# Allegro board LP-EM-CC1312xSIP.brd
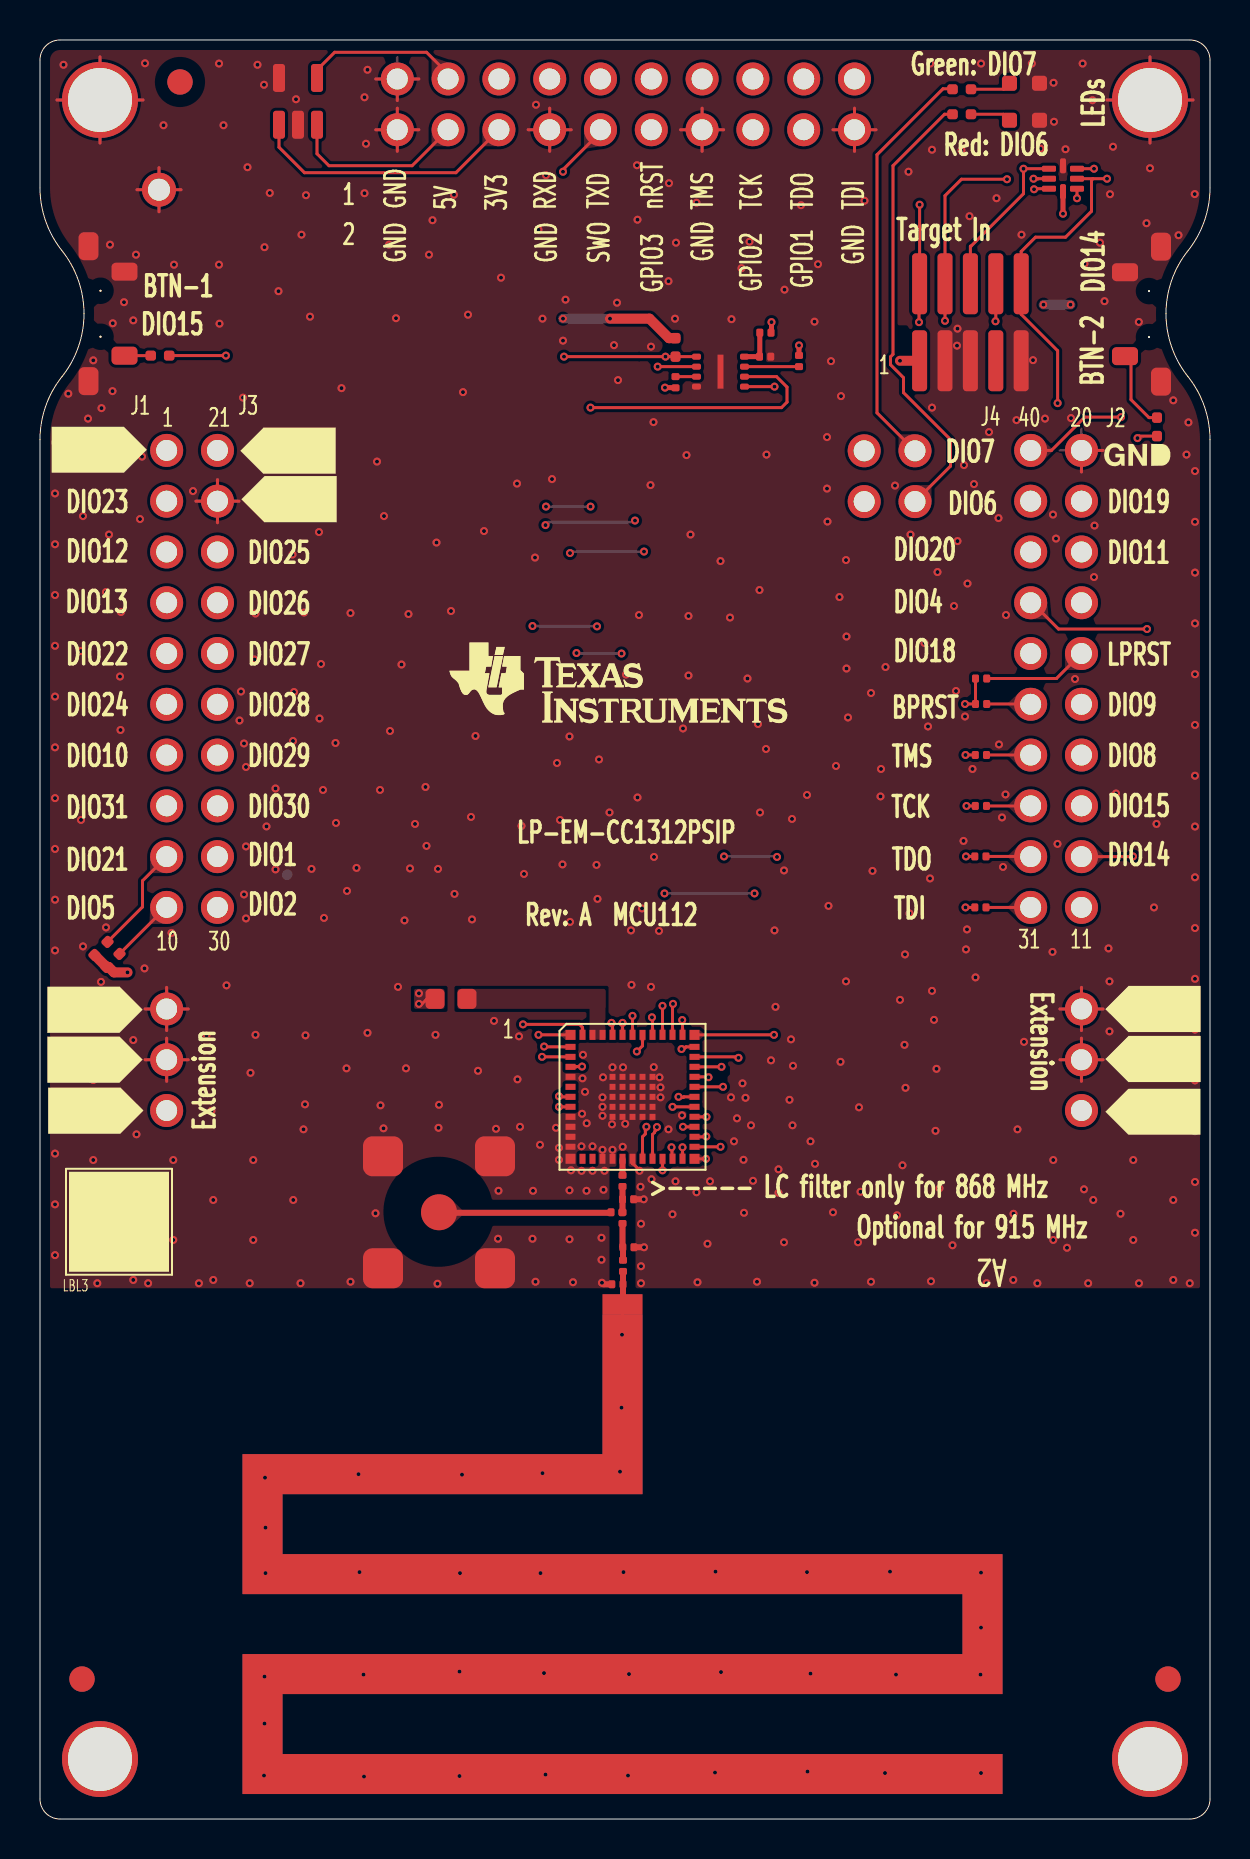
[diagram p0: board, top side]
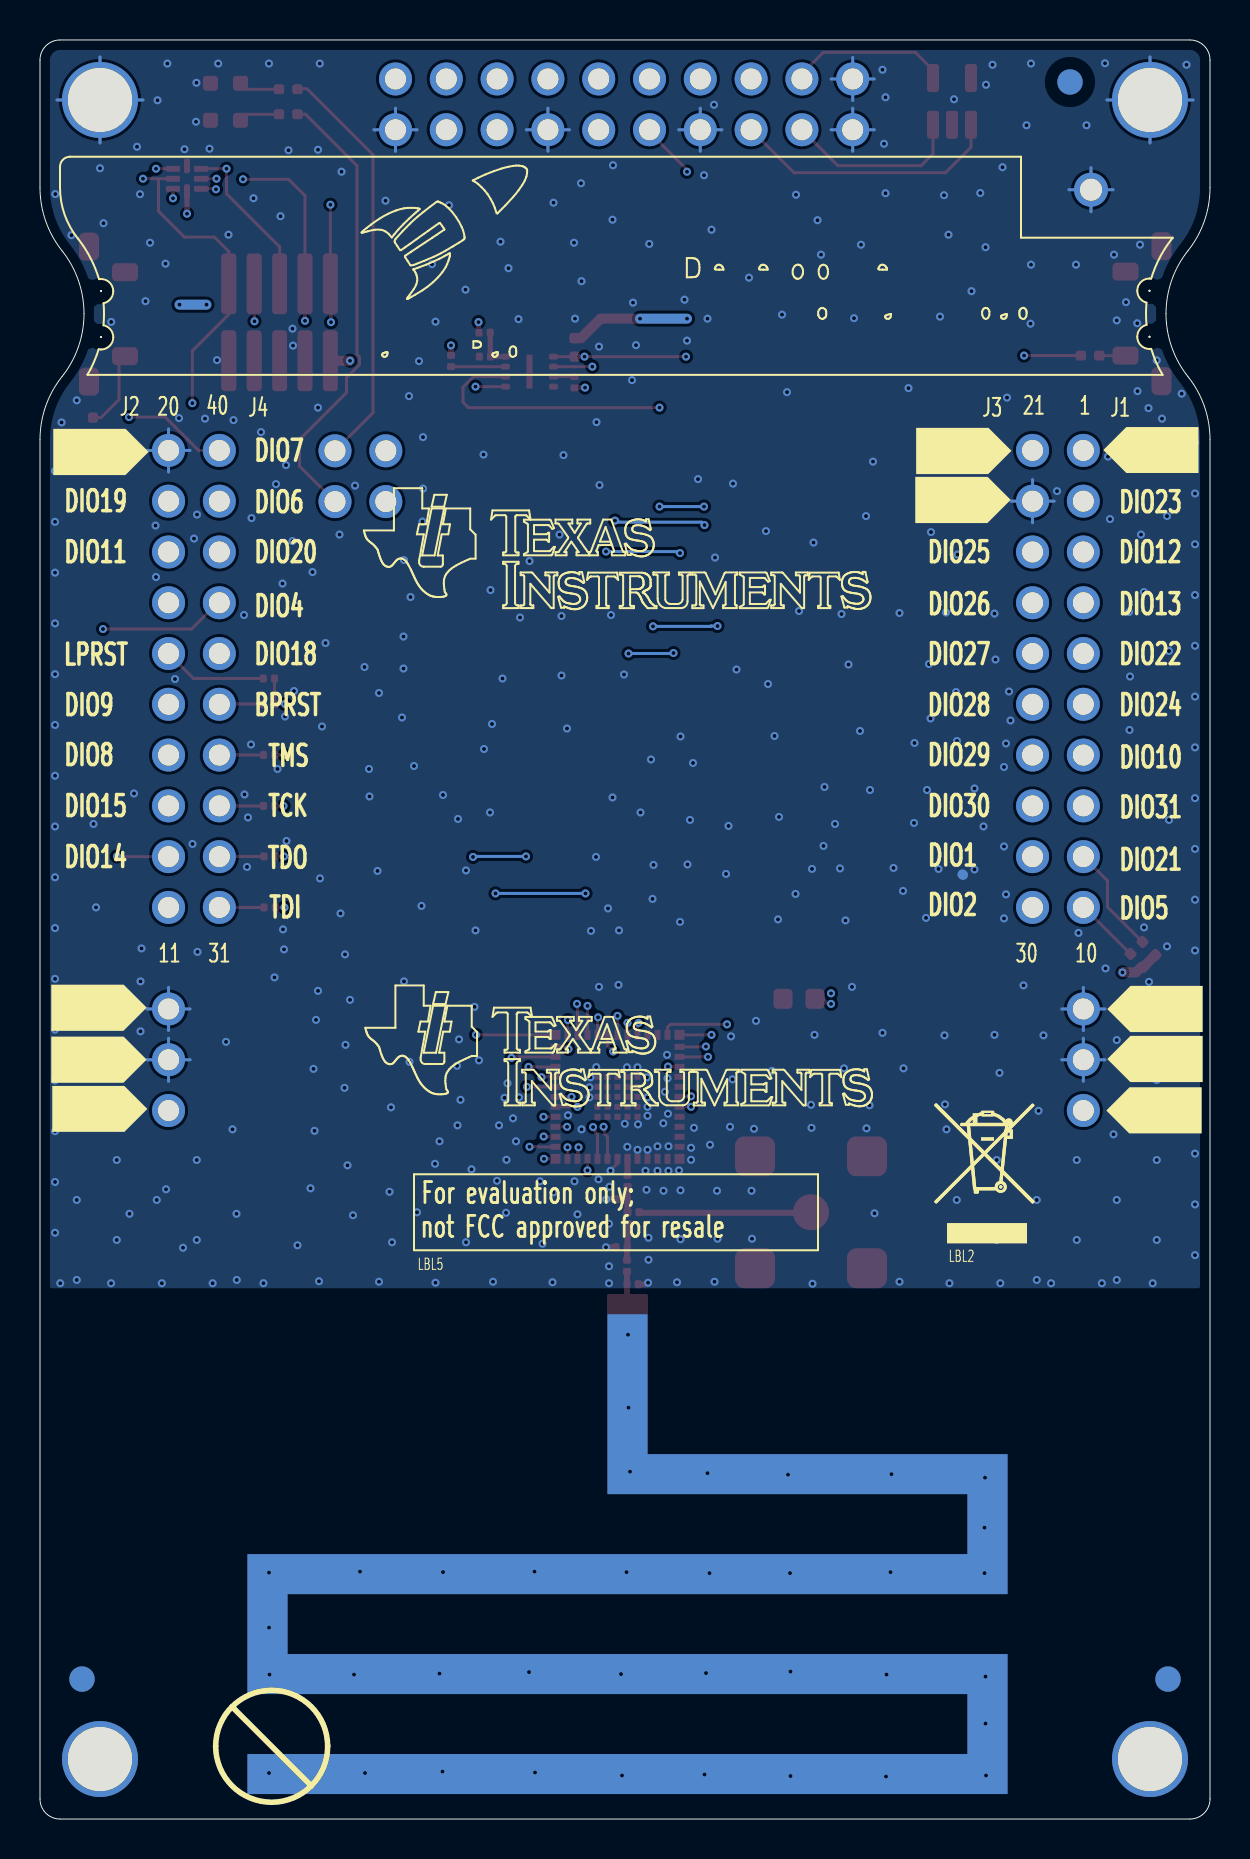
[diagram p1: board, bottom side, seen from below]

Outline 58.5 x 88.99 mm; copper layers: TOP, L2, L3, BOTTOM. Coordinates in mm from the lower left corner of the outline.
Outline path: 0,87.99 0,81.6 arc(0.28,79.93) 1.1,78.45 arc(1.92,76.97) 2.2,75.3 arc(1.92,73.63) 1.1,72.15 arc(0.28,70.67) 0,69 0,1 arc(0.29,0.29) 1,0 57.5,0 arc(58.21,0.29) 58.5,1 58.5,69 arc(58.22,70.67) 57.4,72.15 arc(56.58,73.63) 56.3,75.3 arc(56.58,76.97) 57.4,78.45 arc(58.22,79.93) 58.5,81.6 58.5,87.99 arc(58.21,88.7) 57.5,88.99 1,88.99 arc(0.29,88.7) 0,87.99

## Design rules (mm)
constraint set DEFAULT: min track width 0.15
nets with their own width: min track width 0.15; nets GND VDDS WMCU_VDD

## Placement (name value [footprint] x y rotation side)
A2  868MHz/2440MHz  [ANTENNA_DN024N]  29.12 25.75 180 top
C1  1.8pF  [CAPC0603X35B2N]  29.12 31 0 top
C55  0.1uF  [CAPC0603X35B2N]  35.97 73.15 0 top
C56  100pF  [CAPC0603X35B2N]  28.55 30.35 0 top
C57  100pF  [CAPC0603X35B2N]  29.12 30.35 270 top
CR2  TPD6E004RSE  [QFNFC50P150X150X60-8A2N]  51.85 81.55 90 top
CR4  LPL296-J2L2-25  [LEDC1707X65N]  49.97 86.82 180 top
CR5  LS L296-P2Q2-1  [LEDC1708X67N]  49.97 84.98 180 top
FIDU1  FIDU_1.27mm  [FID127X142]  7 86.89 0 top
FIDU2  FIDU_1.27mm  [FID127X142]  2.1 7 0 top
FIDU3  FIDU_1.27mm  [FID127X142]  56.4 7 0 top
FIDU4  FIDU_1.27mm  [FID127X142]  7 86.89 180 bottom
FIDU5  FIDU_1.27mm  [FID127X142]  2.1 7 180 bottom
FIDU6  FIDU_1.27mm  [FID127X142]  56.4 7 180 bottom
FL2  BLM18HE152SN1  [FIL_BLM18HE152SN1DN]  21.35 41.03 180 top
J1  SSQ-110-23-L-D  [SAMTEC_SSQ11023LD_A2B]  6.33 68.46 0 bottom
J2  SSQ-110-23-L-D  [SAMTEC_SSQ11023LD_A2B]  49.53 68.46 0 bottom
J4  SFH11-PBPC-D10-RA-BK  [SULLINS_SFH11PBPCD10RABK_A2B]  40.72 84.5 90 top
J5  SMA-10V21-TGG  [HUSTSAN_SMA10V21TGGAN]  19.95 30.35 0 top
L1  5.6nH  [INDC0603X33A2N]  29.12 32.2 270 top
LBL1  TI_LOGO  [TI_LOGO_1]  21.47 58.85 0 top
LBL2  TRASH_7mm  [TRASH_7MM]  13.15 28.8 180 bottom
LBL3  ESD_LABEL_5x5mm  [ESD_LABEL_5X5]  1.45 27.38 0 top
LBL5  -  [LABEL_FOR_EVALUATION_ONLY]  39.65 28.6 180 bottom
M1  SNT-100-BK-G  [SAMTEC_SNT100BKG]  44.97 67.18 180 top
M2  SNT-100-BK-G  [SAMTEC_SNT100BKG]  44.97 69.7 180 top
M3  DCB-10  [MECH_DCB10_A2B]  2.86 85.55 180 bottom
M4  DCB-10  [MECH_DCB10_A2B]  55.57 85.79 180 bottom
M5  DCB-10  [MECH_DCB10_A2B]  3 3 180 bottom
M6  DCB-10  [MECH_DCB10_A2B]  55.5 3 180 bottom
MH1  HOLE_3.2mm_PAD_3.8mm_PTH  [MTG320_380]  3 3 0 top
MH2  HOLE_3.2mm_PAD_3.8mm_PTH  [MTG320_380]  55.5 3 0 top
MH3  HOLE_3.2mm_PAD_3.8mm_PTH  [MTG320_380]  3 85.99 0 top
MH4  HOLE_3.2mm_PAD_3.8mm_PTH  [MTG320_380]  55.5 85.99 0 top
MH5  HOLE_1.1mm_PTH  [MTG110_170]  5.95 81.5 0 top
NOREF  -  []  0 85.11 0 top
NOREF#2  -  []  0.02 -28.78 0 top
NOREF#3  -  []  54.51 0 90 top
NOREF#4  -  []  -4.35 67.3 0 top
NOREF#5  -  []  -1.95 35.6 0 top
NOREF#6  -  []  53.05 34 0 top
NOREF#7  -  []  8.35 63.6 0 top
NOREF#8  -  []  -2.05 32.9 0 top
NOREF#9  -  []  0.44 88.82 0 top
NOREF#10  -  []  8.35 65.9 0 top
NOREF#11  -  []  -1.95 38.1 0 top
NOREF#12  -  []  50.47 65.82 0 top
NOREF#13  -  []  0.23 75.46 0 top
NOREF#14  -  []  51.55 35.6 0 top
NOREF#15  -  []  51.55 38.1 0 top
NOREF#16  -  []  -45.65 -52.85 0 top
NOREF#17  -  []  -2.03 88.65 0 top
NOREF#18  -  []  6.85 35.6 180 bottom
NOREF#19  -  []  17.05 63.6 180 bottom
NOREF#20  -  []  6.85 38.1 180 bottom
NOREF#21  -  []  57.95 34.3 180 bottom
NOREF#22  -  []  51.48 89.52 180 bottom
NOREF#23  -  []  6.85 32.9 180 bottom
NOREF#24  -  []  60.25 35.6 180 bottom
NOREF#25  -  []  5.55 67.1 180 bottom
NOREF#26  -  []  60.25 38.2 180 bottom
NOREF#27  -  []  60.15 66 180 bottom
NOREF#28  -  []  17.15 65.9 180 bottom
P1  BB02-HJ041-KB1-603000  [GRADCONN_BB02HJ041KB1603000_A2B]  43.75 65.9 90 top
P2  BB02-HC031-KB1-603000  [GRADCONN_BB02HC031KB1603000_A2B]  6.33 35.44 90 top
P3  BB02-HC031-KB1-603000  [GRADCONN_BB02HC031KB1603000_A2B]  52.07 35.44 90 top
P6  FTSH-105-01-F-DV-K  [SAMTEC_FTSH10501FDVK_A2N]  43.98 72.94 0 top
R2  3.3k  [RESC1005X40B2N]  3.97 43.28 225 top
R3  3.3k  [RESC1005X40B2N]  3.38 43.88 225 top
R4  0  [RESC0603X35B2N]  47.32 53.22 180 top
R5  0  [RESC0603X35B2N]  47.32 50.68 180 top
R6  0  [RESC0603X35B2N]  47.3 48.15 180 top
R7  0  [RESC0603X35B2N]  47.3 45.6 180 top
R9  0  [RESC0603X35B2N]  46.77 55.78 0 top
R11  0  [RESC0603X35B2N]  46.77 57.05 0 top
R12  100  [RESC1005X40B2N]  5.54 73.2 0 top
R13  100  [RESC1005X40B2N]  55.85 70.1 270 top
R14  220  [RESC1005X40B2N]  46.55 86.52 180 top
R15  180  [RESC1005X40B2N]  46.55 85.27 180 top
R22  0  [RESC0603X35B2N]  37.95 72.65 90 top
R23  0  [RESC0603X35B2N]  31.77 72.15 270 top
R24  2.2k  [RESC1005X40B2N]  31.77 73.15 90 top
R25  0  [RESC0603X35B2N]  36.55 74.35 180 top
SW1  1188E-1K2  [SW_1188E1K2V_A2N]  2.42 78.68 270 top
SW2  1188E-1K2  [SW_1188E1K2V_A2N]  56.05 71.9 90 top
U1  CC1312PSIP  [LGAFC73S50P700X700X151]  26.52 39.22 270 top
U3  MX25R8035FZUIL0  [SON50P300X200X60-9B2N]  32.82 73.15 270 top
U4  CAT24C08TDI  [SOT95P280X100-5A2N]  11.95 84.75 0 top
Z9  5.6pF  [CAPC0603X35B2N]  29.7 28.6 180 top
Z10  8.2nH  [INDC0603X33A2N]  29.15 27.95 270 top
Z11  1.8pF  [CAPC0603X35B2N]  29.15 26.75 180 top

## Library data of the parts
A2 = ANTENNA_PCB: User Part Number: #PN
C1 C55-C57 Z9 Z11 = CAPACITOR: User Part Number: #PN; alternate symbols: (CAPC0603X35B2L,CAPC0603X35B2M)
CR2 = DIODE_TVS_TPD6E004_QFN8_V1: User Part Number: #PN; alternate symbols: (QFNFC50P150X150X60-8A2L,QFNFC50P150X150X60-8A2M)
CR4 = LED: alternate symbols: (LEDC1707X65L,LEDC1707X65M)
CR5 = LED: alternate symbols: (LEDC1708X67L,LEDC1708X67M)
FIDU1-FIDU6 = FIDMARK
FL2 = FILTER_2PIN: alternate symbols: (FIL_BLM18HE152SN1DL,FIL_BLM18HE152SN1DM)
J1 J2 = CONN_HEADER_2X10_J_S_V1: User Part Number: #PN; alternate symbols: (SAMTEC_SSQ11023LD_A2C,SAMTEC_SSQ11023LD_A2A)
J4 = CONN_HEADER_2X10_P_V3: User Part Number: #PN; alternate symbols: (SULLINS_SFH11PBPCD10RABK_A2A,SULLINS_SFH11PBPCD10RABK_A2C)
J5 = CONN_COAX_1_4: alternate symbols: (HUSTSAN_SMA10V21TGGL,HUSTSAN_SMA10V21TGGM)
L1 Z10 = INDUCTOR: User Part Number: #PN; alternate symbols: (INDC0603X33A2L,INDC0603X33A2M)
LBL1 = TI_LOGO_V1
LBL2 = TRASH_V2: User Part Number: #PN
LBL3 = ESD_LABEL: User Part Number: #PN
LBL5 = LABEL_FOR_EVALUATOIN_ONLY: User Part Number: #PN
M1 M2 = MECH_SHUNT_JUMPER_V1: User Part Number: #PN
M3-M6 = MECH_SPACERS_SUPPORT_V1: User Part Number: #PN
MH1-MH5 = HOLE_PTH
P1 = CONN_HEADER_2X2_P: User Part Number: #PN; alternate symbols: (GRADCONN_BB02HJ041KB1603000_A2C,GRADCONN_BB02HJ041KB1603000_A2A)
P2 P3 = CONN_HEADER_3_P_S: User Part Number: #PN; alternate symbols: (GRADCONN_BB02HC031KB1603000_A2C,GRADCONN_BB02HC031KB1603000_A2A)
P6 = CONN_HEADER_2X5: User Part Number: #PN; alternate symbols: (SAMTEC_FTSH10501FDVK_A2L,SAMTEC_FTSH10501FDVK_A2M)
R2 R3 R12-R15 R24 = RESISTOR: User Part Number: #PN
R4-R7 R9 R11 R22 R23 R25 = RESISTOR: User Part Number: #PN; alternate symbols: (RESC0603X35B2L,RESC0603X35B2M)
SW1 SW2 = SWITCH_TACT_V2: alternate symbols: (SW_1188E1K2V_A2L,SW_1188E1K2V_A2M)
U1 = IC_RF_CC2652PSIP_LGA73: User Part Number: #PN
U3 = IC_FLASH_MX25R8035F_USON8: User Part Number: #PN; alternate symbols: (SON50P300X200X60-9B2L,SON50P300X200X60-9B2M)
U4 = IC_EEPROM_CAT24C08_TSOT23-5: User Part Number: #PN; alternate symbols: (SOT95P280X100-5A2L,SOT95P280X100-5A2M)

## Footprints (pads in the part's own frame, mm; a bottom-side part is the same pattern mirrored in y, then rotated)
ANTENNA_DN024N
  rect 2x1 smd: 1(0,0)
CAPC0603X35B2N
  custom 0.087x0.087 smd: 1(0,0) 2(0.56,0)
FID127X142
  round 1.27 smd: 1(0,0)
FIL_BLM18HE152SN1DN
  custom 0.237x0.237 smd: 1(0,0) 2(1.6,0)
GRADCONN_BB02HC031KB1603000_A2B
  round 1.65 hole 1.05: 1(0,0) 2(2.54,0) 3(5.08,0)
GRADCONN_BB02HJ041KB1603000_A2B
  round 1.65 hole 1.05: 1(0,0) 2(0,2.54) 3(2.54,0) 4(2.54,2.54)
HUSTSAN_SMA10V21TGGAN
  round 1.8 smd: 1(0,0)
  custom 0.5x0.5 smd: 2(-2.8,-2.8) 3(2.8,-2.8) 4(2.8,2.8) 5(-2.8,2.8)
INDC0603X33A2N
  custom 0.087x0.087 smd: 1(0,0) 2(0.56,0)
LEDC1707X65N
  custom 0.188x0.188 smd: 1(0,0) 2(1.501,0)
LEDC1708X67N
  custom 0.188x0.188 smd: 1(0,0) 2(1.501,0)
LGAFC73S50P700X700X151
  rect 0.5x0.5 smd: 1(0,0) 13(6.2,0) 25(6.2,6.2) 37(0,6.2)
  rect 0.3x0.5 smd: 2(0.6,0) 3(1.1,0) 4(1.6,0) 5(2.1,0) 6(2.6,0) 7(3.1,0) 8(3.6,0) 9(4.1,0) 10(4.6,0) 11(5.1,0) 12(5.6,0) 26(5.6,6.2) 27(5.1,6.2) 28(4.6,6.2) 29(4.1,6.2) 30(3.6,6.2) 31(3.1,6.2) 32(2.6,6.2) 33(2.1,6.2) 34(1.6,6.2) 35(1.1,6.2) 36(0.6,6.2)
  rect 0.5x0.3 smd: 14(6.2,0.6) 15(6.2,1.1) 16(6.2,1.6) 17(6.2,2.1) 18(6.2,2.6) 19(6.2,3.1) 20(6.2,3.6) 21(6.2,4.1) 22(6.2,4.6) 23(6.2,5.1) 24(6.2,5.6) 38(0,5.6) 39(0,5.1) 40(0,4.6) 41(0,4.1) 42(0,3.6) 43(0,3.1) 44(0,2.6) 45(0,2.1) 46(0,1.6) 47(0,1.1) 48(0,0.6)
  rect 0.3x0.3 smd: 49(2.1,2.1) 50(2.1,2.6) 51(2.1,3.1) 52(2.1,3.6) 53(2.1,4.1) 54(2.6,2.1) 55(2.6,2.6) 56(2.6,3.1) 57(2.6,3.6) 58(2.6,4.1) 59(3.1,2.1) 60(3.1,2.6) 61(3.1,3.1) 62(3.1,3.6) 63(3.1,4.1) 64(3.6,2.1) 65(3.6,2.6) 66(3.6,3.1) 67(3.6,3.6) 68(3.6,4.1) 69(4.1,2.1) 70(4.1,2.6) 71(4.1,3.1) 72(4.1,3.6) 73(4.1,4.1)
MTG110_170
  round 1.699 hole 1.1: 1(0,0)
MTG320_380
  round 3.8 hole 3.2: 1(0,0)
QFNFC50P150X150X60-8A2N
  custom 0.075x0.075 smd: 1(0,0) 2(0.5,0) 3(1,0) 4(1.145,0.7) 5(1,1.4) 6(0.5,1.4) 7(0,1.4) 8(-0.145,0.7)
RESC0603X35B2N
  custom 0.087x0.087 smd: 1(0,0) 2(0.56,0)
RESC1005X40B2N
  custom 0.125x0.125 smd: 1(0,0) 2(0.924,0)
SAMTEC_FTSH10501FDVK_A2N
  custom 0.188x0.188 smd: 1(0,0) 2(0,3.85) 3(1.27,0) 4(1.27,3.85) 5(2.54,0) 6(2.54,3.85) 7(3.81,0) 8(3.81,3.85) 9(5.08,0) 10(5.08,3.85)
SAMTEC_SSQ11023LD_A2B
  round 1.65 hole 1.05: 1(0,0) 2(2.54,0) 3(0,2.54) 4(2.54,2.54) 5(0,5.08) 6(2.54,5.08) 7(0,7.62) 8(2.54,7.62) 9(0,10.16) 10(2.54,10.16) 11(0,12.7) 12(2.54,12.7) 13(0,15.24) 14(2.54,15.24) 15(0,17.78) 16(2.54,17.78) 17(0,20.32) 18(2.54,20.32) 19(0,22.86) 20(2.54,22.86)
SON50P300X200X60-9B2N
  custom 0.075x0.075 smd: 1(0,0) 2(0.5,0) 3(1,0) 4(1.5,0) 5(1.5,2.4) 6(1,2.4) 7(0.5,2.4) 8(0,2.4)
  rect 1.7x0.3 smd: 9(0.75,1.2)
SOT95P280X100-5A2N
  custom 0.15x0.15 smd: 1(0,0) 2(0.95,0) 3(1.9,0) 4(1.9,2.34) 5(0,2.34)
SULLINS_SFH11PBPCD10RABK_A2B
  round 1.65 hole 1.05: 1(0,0) 2(2.54,0) 3(0,2.54) 4(2.54,2.54) 5(0,5.08) 6(2.54,5.08) 7(0,7.62) 8(2.54,7.62) 9(0,10.16) 10(2.54,10.16) 11(0,12.7) 12(2.54,12.7) 13(0,15.24) 14(2.54,15.24) 15(0,17.78) 16(2.54,17.78) 17(0,20.32) 18(2.54,20.32) 19(0,22.86) 20(2.54,22.86)
SW_1188E1K2V_A2N
  round 0.099 hole 0.899 unplated: (2.229,0.6) (4.529,0.6)
  custom 0.25x0.25 smd: 1(0,0) 2(6.75,0)
  custom 0.225x0.225 smd: 3(1.275,1.8) 4(5.475,1.8)

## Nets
5V0_BP: J1.2 J4.18 P2.1 U4.4
GND: C1.2 C55.2 CR2.4 CR4.1(C) CR5.1(C) J1.4 J2.2 J4.1 J4.7 J4.13 J4.19 J4.20 J5.2 J5.3 J5.4 J5.5 MH3.1 MH4.1 MH5.1 P2.2 P2.3 P3.2 P3.3 P6.3 P6.5 P6.9 SW1.1 SW1.2 SW1.3 SW2.1 SW2.2 SW2.4 U1.5 U1.9 U1.10 U1.11 U1.12 U1.13 U1.16 U1.17 U1.19 U1.49 U1.50 U1.51 U1.52 U1.53 U1.54 U1.55 U1.56 U1.57 U1.58 U1.59 U1.60 U1.61 U1.62 U1.63 U1.64 U1.65 U1.66 U1.67 U1.68 U1.69 U1.70 U1.71 U1.72 U1.73 U3.4 U3.9 U4.2 U4.5(WP) Z9.1 Z11.2
VDDS: FL2.1 U1.46 U1.47(VDDS_PU)
BP_RESET: J2.11 R9.2
DIO1: J1.18 U1.21
DIO2: J1.20 U1.20
DIO4: J2.7 U1.22
DIO5_SDA: J1.19 R2.1 U1.23
DIO6_RLED: J2.3 P1.2 U1.24
DIO7_GLED: J2.1 P1.4 U1.25
DIO8_MISO: J2.14 U1.26 U3.2
DIO9_MOSI: J2.12 U1.27 U3.5
DIO10_SCLK: J1.13 U1.28 U3.6
DIO11_CS: J2.6 U1.29
DIO14_BTN2: J2.18 R13.2 U1.32
DIO15_BTN1: J2.16 R12.2 U1.33
DIO19_CTS: J2.4 U1.40
DIO20_FLASH_CS: J2.5 R24.1 U1.41 U3.1
DIO21_SCL: J1.17 R3.1 U1.42
DIO22: J1.9 U1.43
DIO23_ANALOG: J1.3 U1.44
DIO24_ANALOG: J1.11 U1.45
DIO25_ANALOG: J1.6 U1.48
DIO26_ANALOG: J1.8 U1.1
DIO27_ANALOG: J1.10 U1.2
DIO28: J1.12 U1.3
DIO29: J1.14 U1.7
DIO30: J1.16 U1.8
DIO31: J1.15 U1.38
LP_RESET: J2.10 R11.2
RESET: CR2.2 J4.10 P6.10 R9.1 R11.1 U1.4
RXD: J1.5 J4.14 U1.30
SWO: CR2.1 J2.9 J4.11 U1.39
TCK: CR2.6 J4.6 P6.4 R5.2 U1.35
TDI: CR2.3 J4.2 P6.8 R7.2 U1.37
TDO: CR2.5 J4.4 P6.6 R6.2 U1.36
TMS: CR2.7 J4.8 P6.2 R4.2 U1.34
TXD: J1.7 J4.12 U1.31
WMCU_VDD: CR2.8(VCC) FL2.2 J1.1 J4.16 P3.1 P6.1 R2.2 R3.2 R22.2 R23.2 R24.2 R25.1
XDS_BOARDID_SCL: J4.15 U4.1
XDS_BOARDID_SDA: J4.17 U4.3
N3109894: J2.13 R4.1
N3109960: J2.15 R5.1
N3110034: J2.17 R6.1
N3110086: J2.19 R7.1
N3110356: P1.1 R15.2
N3110380: P1.3 R14.2
N3110768: R12.1 SW1.4
N3110772: R13.1 SW2.3
N3110876: CR4.2 R14.1
N3110880: CR5.2 R15.1
N3111246: C55.1 R25.2 U3.8(VCC)
N3111262: R22.1 U3.7
N3111266: R23.1 U3.3
N3450237: C56.1 J5.1
N3450301: C1.1 C56.2 C57.1 L1.2
N3495961: C57.2 Z9.2 Z10.1
N3495979: A2.1 Z10.2 Z11.1
N3510597: L1.1 U1.18

Pads without a net: FIDU1 1; FIDU2 1; FIDU3 1; FIDU4 1; FIDU5 1; FIDU6 1; J2 8 20; J4 3 5 9; MH1 1; MH2 1; P6 7; U1 6 14 15

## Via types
v1: diameter 0.4, hole 0.2, TOP to BOTTOM, 592 vias

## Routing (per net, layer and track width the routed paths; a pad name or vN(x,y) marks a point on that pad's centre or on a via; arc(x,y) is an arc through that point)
5V0_BP: length 75.1
  TOP w0.15: U4.4 13.85,87.49 14.73,88.38 19.32,88.38 20.41,87.3 J4.18
  L3 w0.5: J1.2 7.7,69.63 ; 7.7,69.63 7.7,74.93 10.15,77.38 14.62,77.38 19.18,81.93 19.18,85.73 20.41,86.95 J4.18 ; 7.7,69.63 7.56,69.78 5.82,69.78 1.45,65.4 1.45,40.32 P2.1
GND: length 263.5
  TOP w0.15: P3.3 53.15,40.52 ; P3.3 51,40.52 ; P3.3 52.07,39.44 ; P3.3 52.07,41.6 ; 33.1,83.42 J4.7 ; J4.7 34.18,84.5 ; J4.7 33.1,85.58 ; J4.7 32.03,84.5 ; 16.79,87.04 J4.20 ; J4.20 18.94,87.04 ; J4.20 17.86,85.96 ; 40.72,83.42 J4.1 ; J4.1 39.65,84.5 ; J4.1 40.72,85.58 ; J4.1 41.8,84.5 ; 16.79,84.5 J4.19 ; J4.19 17.86,83.42 ; J4.19 18.94,84.5 ; J4.19 17.86,85.58 ; v1(29.97,32.43) 29.97,32.46 29.66,32.78 29.62,32.78 29.62,33.03 ; MH4.1 55.5,88.14 ; MH4.1 53.35,85.99 ; MH4.1 57.65,85.99 ; MH4.1 55.5,83.84 ; 6.33,36.9 P2.2 ; P2.2 5.26,37.98 ; P2.2 7.41,37.98 ; P2.2 6.33,39.06 ; P2.3 6.33,41.6 ; P2.3 7.41,40.52 ; P2.3 6.33,39.44 ; P2.3 5.26,40.52 ; J4.13 26.56,84.5 ; J4.13 25.48,85.58 ; J4.13 24.41,84.5 ; J4.13 25.48,83.42 ; J1.4 8.87,67 ; J1.4 9.95,65.92 ; J1.4 7.8,65.92 ; J1.4 8.87,64.84 ; 30.17,28.63 v1(30.2,28.6) ; MH5.1 5.95,82.6 ; MH5.1 5.95,80.4 ; MH5.1 4.85,81.5 ; MH5.1 7.05,81.5 ; 0.85,85.99 MH3.1 ; MH3.1 5.15,85.99 ; MH3.1 3,83.84 ; MH3.1 3,88.14 ; 51,37.98 P3.2 ; P3.2 52.07,39.06 ; P3.2 52.07,36.9 ; P3.2 53.15,37.98 ; 53.15,68.46 J2.2 52.07,67.38
  TOP w0.3: Z11.2 28.17,26.75 v1(28.1,26.82) ; C1.2 v1(30.19,31) ; Z9.1 v1(30.2,28.6)
  L2 w0.15: P2.3 6.33,41.6 ; P2.3 7.41,40.52 ; P2.3 6.33,39.44 ; P2.3 5.26,40.52 ; 51,37.98 P3.2 ; P3.2 53.15,37.98 ; P3.2 52.07,39.06 ; P3.2 52.07,36.9 ; 17.86,85.96 J4.20 ; J4.20 16.79,87.04 ; J4.20 18.94,87.04 ; J4.20 17.86,88.12 ; J2.2 53.15,68.46 ; J2.2 52.07,67.38 ; J2.2 52.07,69.54 ; J2.2 51,68.46 ; P2.2 7.41,37.98 ; P2.2 6.33,36.9 ; P2.2 6.33,39.06 ; P2.2 5.26,37.98 ; 25.48,83.42 J4.13 ; J4.13 24.41,84.5 ; J4.13 25.48,85.58 ; J4.13 26.56,84.5 ; 8.87,64.84 J1.4 ; J1.4 8.87,67 ; J1.4 7.8,65.92 ; J1.4 9.95,65.92 ; 17.86,83.42 J4.19 ; J4.19 18.94,84.5 ; J4.19 17.86,85.58 ; J4.19 16.79,84.5 ; 4.85,81.5 MH5.1 ; MH5.1 5.95,82.6 ; MH5.1 5.95,80.4 ; MH5.1 7.05,81.5 ; J4.1 40.72,85.58 ; J4.1 41.8,84.5 ; J4.1 39.65,84.5 ; J4.1 40.72,83.42 ; MH4.1 55.5,88.14 ; MH4.1 57.65,85.99 ; MH4.1 53.35,85.99 ; MH4.1 55.5,83.84 ; 52.07,39.44 P3.3 ; P3.3 53.15,40.52 ; P3.3 52.07,41.6 ; P3.3 51,40.52 ; J4.7 33.1,85.58 ; J4.7 33.1,83.42 ; J4.7 32.03,84.5 ; J4.7 34.18,84.5 ; MH3.1 5.15,85.99 ; MH3.1 3,83.84 ; MH3.1 3,88.14 ; MH3.1 0.85,85.99
  L3 w0.15: P3.3 52.07,41.6 ; P3.3 53.15,40.52 ; P3.3 52.07,39.44 ; 33.1,83.42 J4.7 32.03,84.5 ; 52.07,36.9 P3.2 ; P3.2 52.07,39.06 ; P3.2 53.15,37.98 ; 24.41,84.5 J4.13 ; J4.13 25.48,83.42 ; J4.13 25.48,85.58 ; J4.1 41.8,84.5 ; J4.1 39.65,84.5 ; J4.1 40.72,83.42 ; 16.79,84.5 J4.19 ; J4.19 17.86,83.42 ; J4.19 17.86,85.58 ; 6.33,39.44 P2.3 ; P2.3 5.26,40.52 ; P2.3 7.41,40.52 ; 52.07,69.54 J2.2 51.21,69.32 ; 17.86,85.96 J4.20 ; J4.20 18.94,87.04 ; J4.20 16.79,87.04 ; J4.20 17.86,88.12 ; 5.95,80.4 MH5.1 ; MH5.1 7.05,81.5 ; MH5.1 5.95,82.6 ; MH5.1 4.85,81.5 ; P2.2 7.41,37.98 ; P2.2 5.26,37.98 ; P2.2 6.33,39.06 ; P2.2 6.33,36.9 ; 55.5,83.84 MH4.1 ; MH4.1 53.35,85.99 ; MH4.1 55.5,88.14 ; MH4.1 57.65,85.99 ; 0.85,85.99 MH3.1 ; MH3.1 5.15,85.99 ; MH3.1 3,83.84 ; MH3.1 3,88.14 ; J1.4 9.95,65.92 ; J1.4 8.87,64.84 ; J1.4 7.8,65.92
  BOTTOM w0.15: J4.1 40.72,85.58 ; J4.1 41.8,84.5 ; J4.1 40.72,83.42 ; J4.1 39.65,84.5 ; 52.07,67.38 J2.2 ; J2.2 53.15,68.46 ; J2.2 52.07,69.54 ; J2.2 51,68.46 ; 25.48,83.42 J4.13 ; J4.13 24.41,84.5 ; J4.13 25.48,85.58 ; J4.13 26.56,84.5 ; 52.07,36.9 P3.2 ; P3.2 53.15,37.98 ; P3.2 52.07,39.06 ; P3.2 51,37.98 ; MH3.1 5.15,85.99 ; MH3.1 3,83.84 ; MH3.1 3,88.14 ; MH3.1 0.85,85.99 ; 16.79,87.04 J4.20 ; J4.20 18.94,87.04 ; J4.20 17.86,85.96 ; J4.20 17.86,88.12 ; 17.86,83.42 J4.19 ; J4.19 16.79,84.5 ; J4.19 17.86,85.58 ; J4.19 18.94,84.5 ; P3.3 53.15,40.52 ; P3.3 52.07,41.6 ; P3.3 52.07,39.44 ; P3.3 51,40.52 ; 7.8,65.92 J1.4 ; J1.4 8.87,67 ; J1.4 8.87,64.84 ; J1.4 9.95,65.92 ; P2.2 6.33,39.06 ; P2.2 6.33,36.9 ; P2.2 5.26,37.98 ; P2.2 7.41,37.98 ; 4.85,81.5 MH5.1 ; MH5.1 5.95,80.4 ; MH5.1 7.05,81.5 ; MH5.1 5.95,82.6 ; MH4.1 57.65,85.99 ; MH4.1 55.5,88.14 ; MH4.1 55.5,83.84 ; MH4.1 53.35,85.99 ; 33.1,83.42 J4.7 ; J4.7 32.03,84.5 ; J4.7 34.18,84.5 ; J4.7 33.1,85.58 ; P2.3 7.41,40.52 ; P2.3 6.33,39.44 ; P2.3 6.33,41.6 ; P2.3 5.26,40.52
  BOTTOM w0.5: 12.35,47.23 12.38,47.25
  vias: v1(0.75,68.85) v1(0.75,66.31) v1(0.75,63.77) v1(0.75,61.23) v1(0.75,58.69) v1(0.75,56.15) v1(0.75,53.61) v1(0.75,51.07) v1(0.75,48.53) v1(0.75,45.99) v1(0.75,43.45) v1(0.75,40.91) v1(0.75,38.37) v1(0.75,35.83) v1(0.75,33.29) v1(0.75,30.75) v1(0.75,28.21) v1(1.17,87.75) v1(1.41,71.3) v1(2.05,58.43) v1(2.05,49.97) v1(2.15,65.18) v1(2.15,43.65) v1(2.4,70.05) v1(2.66,72.97) v1(2.66,68.97) v1(2.66,36.97) v1(2.66,32.97) v1(2.66,28.97) v1(2.87,26.8) v1(3.07,70.57) v1(3.05,41.88) v1(3.3,61.38) v1(3.3,44.6) v1(3.45,64.25) v1(3.5,78.75) v1(3.64,74.82) v1(3.62,71.43) v1(4.05,60.38) v1(4,57.15) v1(4.02,54.47) v1(4.2,75.88) v1(4.66,74.97) v1(4.66,38.97) v1(4.66,30.97) v1(4.66,26.97) v1(4.8,78.25) v1(4.82,34.25) v1(5,65.03) v1(5.1,68.15) v1(5.25,87.82) v1(5.22,42.55) v1(5.41,26.8) v1(6.17,84.73) v1(6.57,44.32) v1(6.66,32.97) v1(6.66,28.97) v1(6.7,77.75) v1(7.65,66.43) v1(7.95,26.8) v1(8.32,39.2) v1(8.57,35.43) v1(8.66,30.97) v1(8.66,26.97) v1(8.95,87.81) v1(8.95,77.75) v1(8.97,74.8) v1(9.17,84.73) v1(9.32,41.7) v1(9.97,54.95) v1(10.05,56.4) v1(10.15,71.1) v1(10.2,53.8) v1(10.2,46.25) v1(10.3,52.62) v1(10.3,48.65) v1(10.3,45.05) v1(10.38,82.62) v1(10.49,26.8) v1(10.52,37.32) v1(10.66,32.97) v1(10.66,28.97) v1(10.77,60.3) v1(10.72,58) v1(10.77,39.22) v1(10.88,87.75) v1(11.2,86.75) v1(11.22,78.62) v1(11.32,49.65) v1(11.49,81.34) v1(11.77,51.55) v1(11.77,47.5) v1(11.92,76.43) v1(12.62,63.25) v1(12.65,53.93) v1(12.66,30.97) v1(12.8,86.02) v1(12.7,56.38) v1(13.07,79.25) v1(13.03,26.8) v1(13.2,60.35) v1(13.17,34.5) v1(13.3,81.23) v1(13.27,39.2) v1(13.25,35.75) v1(13.5,75.15) v1(13.57,47.53) v1(13.95,64.38) v1(13.97,55.05) v1(14.05,57.78) v1(14.15,51.47) v1(14.2,45.07) v1(14.77,53.82) v1(14.8,49.82) v1(15.07,71.57) v1(15.35,46.43) v1(15.32,37.55) v1(15.52,60.32) v1(15.52,26.88) v1(15.82,47.57) v1(16.22,86.12) v1(16.3,83.8) v1(16.22,81.32) v1(16.38,87.5) v1(16.38,39.32) v1(16.77,30.3) v1(16.85,67.9) v1(17,51.47) v1(17.02,35.7) v1(17.2,65.18) v1(17.17,34.55) v1(17.45,78.75) v1(17.5,54.43) v1(17.8,75.07) v1(17.9,41.62) v1(18.07,57.75) v1(18.22,44.95) v1(18.3,37.55) v1(18.42,60.28) v1(18.5,47.55) v1(18.75,49.78) v1(19.27,51.62) v1(19.32,48.68) v1(19.45,78.25) v1(19.62,79.97) v1(19.77,39.22) v1(19.82,63.85) v1(19.9,47.53) v1(19.88,26.78) v1(19.95,35.72) v1(19.92,34.57) v1(20.55,60.43) v1(20.7,81.25) v1(20.72,46.28) v1(21.15,71.38) v1(21.4,75.25) v1(21.55,50.12) v1(21.6,45) v1(21.77,54.18) v1(21.9,37.43) v1(22.2,64.43) v1(22.1,56.78) v1(22.7,39.93) v1(22.8,34.53) v1(22.9,29.03) v1(22.92,31.43) v1(23.05,77.1) v1(23.67,57.5) v1(23.85,66.8) v1(23.88,37) v1(23.95,39.15) v1(24.07,49.68) v1(24,34.62) v1(24.2,47.28) v1(24.65,31.43) v1(24.62,29.03) v1(24.8,85.75) v1(24.75,63.1) v1(24.77,26.88) v1(24.92,79.5) v1(25,33.72) v1(25.12,75.05) v1(25.3,82.23) v1(25.6,67.03) v1(25.8,34.57) v1(25.85,52.82) v1(25.95,33.57) v1(25.95,32.97) v1(26,49.97) v1(26.15,73.95) v1(26.12,47.75) v1(26.27,76) v1(26.47,54.15) v1(26.47,31.45) v1(26.47,29) v1(26.5,44.88) v1(26.55,32.45) v1(26.65,26.85) v1(27.07,33.65) v1(27.08,32.42) v1(27.15,38.22) v1(27.12,37.05) v1(27.1,35.28) v1(27.25,36.38) v1(27.33,34.8) v1(27.32,31.43) v1(27.62,33.65) v1(27.62,32.43) v1(27.82,47.72) v1(27.88,46.03) v1(27.95,53) v1(28.04,78.79) v1(28.07,29.07) v1(28.07,27.97) v1(28.15,37.1) v1(28.12,36.1) v1(28.12,35.62) v1(28.12,35.18) v1(28.12,33.47) v1(28.17,31.47) v1(28.22,32.43) v1(28.47,50.35) v1(28.62,37.6) v1(28.6,34.75) v1(28.62,33.47) v1(28.7,73.72) v1(28.85,75.85) v1(28.9,71.97) v1(29.15,37.6) v1(29.13,33.62) v1(29.3,57.25) v1(29.26,34.78) v1(29.55,44.45) v1(29.57,41.72) v1(29.85,82.73) v1(29.88,80) v1(29.88,51.1) v1(29.95,60.22) v1(30.02,31.62) v1(30.05,29.78) v1(30.05,27.65) v1(30.05,26.8) v1(30.1,45.55) v1(30.55,73.65) v1(30.52,66.72) v1(30.55,41.62) v1(30.57,32) v1(30.67,69.88) v1(30.69,37.61) v1(30.7,48.12) v1(30.95,44.43) v1(30.97,37.1) v1(31.02,36.6) v1(31.02,36.1) v1(31.45,81.82) v1(31.42,76.93) v1(31.42,34.5) v1(31.62,30.25) v1(31.8,78.85) v1(31.75,75.05) v1(31.77,31.9) v1(32.15,54.55) v1(32.1,35.2) v1(32.32,68.22) v1(32.42,60.18) v1(32.42,57.2) v1(32.52,64.25) v1(32.82,80.85) v1(32.82,31.35) v1(32.88,26.85) v1(33.38,28.78) v1(33.5,31.9) v1(34.02,62.93) v1(34.57,75.03) v1(34.5,60.1) v1(34.55,36.1) v1(34.7,33.9) v1(34.85,35.05) v1(35.07,77.57) v1(35.12,36.8) v1(35.17,32.97) v1(35.2,30.32) v1(35.27,36.07) v1(35.38,57.05) v1(35.47,78.9) v1(35.55,34.7) v1(35.65,31.93) v1(35.9,54.78) v1(35.85,26.88) v1(35.97,61.47) v1(36,50.35) v1(36.3,53.53) v1(36.32,68.25) v1(36.55,37.95) v1(36.72,44.45) v1(36.77,40.62) v1(36.92,32.5) v1(36.92,31.32) v1(37.2,47.45) v1(37.2,28.85) v1(37.22,76.5) v1(37.47,35.97) v1(37.55,39) v1(37.6,50.03) v1(37.65,37.68) v1(37.62,34.7) v1(38.05,80.73) v1(38.35,51.22) v1(38.52,33.9) v1(38.72,74.9) v1(38.75,32.78) v1(38.72,26.82) v1(38.9,77.78) v1(39.35,69.12) v1(39.35,66.55) v1(39.38,64.9) v1(39.42,45.68) v1(39.55,72.93) v1(39.65,30.35) v1(39.8,52.68) v1(39.97,61.12) v1(40.05,71.18) v1(40.02,37.88) v1(40.3,62.97) v1(40.3,41.9) v1(40.32,59.15) v1(40.32,57.55) v1(40.4,55.1) v1(40.9,28.85) v1(40.95,35.6) v1(41.02,31.38) v1(41.22,80.95) v1(41.55,56.32) v1(41.55,26.88) v1(41.62,47.43) v1(42.05,52.53) v1(42.02,51.15) v1(42.27,57.62) v1(42.75,66.7) v1(42.85,30.2) v1(43,40.97) v1(43.12,32.7) v1(43.25,43.25) v1(43.22,38.72) v1(43.27,36.57) v1(43.42,82.4) v1(43.47,45.3) v1(43.52,64.25) v1(44.22,58.82) v1(44.4,54.65) v1(44.51,87.81) v1(44.5,47.05) v1(44.55,26.9) v1(44.6,83.5) v1(44.6,70.6) v1(44.6,41.43) v1(44.7,39.97) v1(44.77,34.43) v1(44.88,62.38) v1(44.82,37.53) v1(44.97,31.55) v1(45.62,28.7) v1(45.7,60.68) v1(45.8,56.43) v1(45.88,74.55) v1(45.85,73.7) v1(45.88,63.93) v1(46.07,83.48) v1(46.2,67.72) v1(46.17,48.93) v1(46.25,55.15) v1(46.3,43.5) v1(46.38,61.8) v1(46.35,44.5) v1(46.47,80.18) v1(46.62,52.53) v1(46.7,66.78) v1(46.77,42.1) v1(47.05,87.81) v1(47.33,26.8) v1(47.45,69.38) v1(47.82,81.07) v1(47.92,65.07) v1(47.95,53.75) v1(48.1,50.1) v1(48.15,47.62) v1(48.3,60.22) v1(48.27,51.25) v1(48.67,30.28) v1(48.66,26.97) v1(48.82,69.97) v1(48.88,34.5) v1(49.07,79.25) v1(49.2,38.88) v1(49.59,87.81) v1(49.65,72.97) v1(49.87,26.8) v1(50.02,83.55) v1(50.25,70.05) v1(50.68,86.85) v1(50.65,65.25) v1(50.62,43.38) v1(50.66,32.97) v1(50.66,28.97) v1(50.7,84.9) v1(50.8,64.05) v1(50.88,48.78) v1(51.27,83.52) v1(51.35,28.57) v1(51.55,70.07) v1(51.75,57.03) v1(52.13,87.81) v1(52.2,31.5) v1(52.22,77.8) v1(52.41,26.8) v1(52.62,85.98) v1(52.66,30.97) v1(52.72,64.7) v1(52.7,62.12) v1(53,78.85) v1(53.22,75.93) v1(53.42,43.55) v1(53.47,41.9) v1(53.47,39.4) v1(53.5,81.27) v1(53.65,83.65) v1(53.8,51.3) v1(54.02,30.28) v1(54.66,32.97) v1(54.66,28.97) v1(54.94,74.89) v1(54.95,26.8) v1(55.25,35.97) v1(55.32,79.82) v1(55.5,82.57) v1(55.7,45.6) v1(55.82,49.78) v1(56.45,40.8) v1(56.52,38.12) v1(56.66,70.97) v1(56.66,34.97) v1(56.66,30.97) v1(56.66,26.97) v1(56.93,79.22) v1(57.32,68.25) v1(57.42,69.86) v1(57.49,26.8) v1(57.74,81.28) v1(57.75,67.43) v1(57.75,64.89) v1(57.75,62.35) v1(57.75,59.81) v1(57.75,57.27) v1(57.75,54.73) v1(57.75,52.19) v1(57.75,49.65) v1(57.75,47.11) v1(57.75,44.57) v1(57.75,42.03) v1(57.75,39.49) v1(57.75,36.95) v1(57.75,34.41) v1(57.75,31.87) v1(57.75,29.33)
BP_RESET: length 2.2
  TOP w0.15: J2.11 49.52,55.78 R9.2
DIO1: length 32.7
  TOP w0.15: 30.62,33.03 30.63,33.03 30.63,34.24 30.72,34.34 30.72,34.37 30.85,34.5 v1(30.85,34.61)
  L3 w0.15: v1(30.85,34.61) 30.85,34.7 30.41,35.13 30.41,35.68 30.3,35.8 30.3,35.82 29.94,36.19 29.94,37.33 29.92,37.35 29.92,37.95 29.94,37.97 30.02,37.97 30.27,38.22 30.27,38.69 30.14,38.82 29.66,38.82 29.47,38.63 29.05,38.63 29.05,38.63 28.22,38.63 27.47,39.37 27.47,40.95 20.28,48.14 J1.18
DIO2: length 30.1
  TOP w0.15: 30.12,33.03 30.12,34.12 30.27,34.27 30.27,34.52 30.32,34.57 v1(30.32,34.63)
  L3 w0.15: v1(30.32,34.63) 30.11,34.83 30.11,35.16 29.57,35.7 29.57,37.42 29.58,37.42 29.58,37.78 29.57,37.78 29.57,37.88 29.42,38.03 29.33,38.03 29.33,38.03 28.97,38.03 28.97,38.03 28.8,38.03 28.8,38.03 28.45,38.03 28.44,38.03 27.97,38.03 26.88,39.12 26.88,40.7 21.97,45.6 J1.20
DIO4: length 49.8
  TOP w0.15: v1(55.35,59.53) 50.92,59.53 49.61,60.84 J2.7 ; 31.12,33.03 v1(31.12,32.45)
  L3 w0.15: v1(55.35,59.53) 55.35,50.57 54.22,49.45 54.22,47.97 54.25,47.95 54.25,45.87 52.36,43.97 47.69,43.97 45.02,41.31 45.02,41.25 44.78,41 44.55,41 36.02,32.47 31.15,32.47 v1(31.12,32.45)
DIO5_SDA: length 38
  TOP w0.15: R2.1 6.3,45.6 J1.19 ; 31.62,33.03 31.6,33.05 31.6,33.58 v1(31.57,33.6)
  L3 w0.15: v1(31.57,33.6) 30.27,33.6 29.56,34.31 29.48,34.31 29.44,34.35 28.8,34.35 28.78,34.32 28.42,34.32 28.4,34.35 27.95,34.35 27.93,34.38 26.87,34.38 26.86,34.39 26.63,34.39 25.9,35.12 25.65,35.12 25.22,35.55 25.22,36.45 25.32,36.56 25.32,37.74 25.95,38.36 25.95,40.35 22.38,43.93 8.07,43.93 6.4,45.6 J1.19
DIO6_RLED: length 101.9
  TOP w0.15: v1(32.12,33.6) 32.12,33.03
  L3 w0.15: v1(29.75,64.95) 30.7,65.9 P1.2 41.25,65.9 42.6,67.25 48.22,67.25 49.53,65.94 J2.3 ; v1(32.12,33.6) 32.12,33.4 31.88,33.15 30.3,33.15 29.53,33.92 29.44,33.92 29.31,34.05 28.96,34.05 28.93,34.03 28.3,34.03 28.27,34.05 27.83,34.05 27.8,34.07 26.75,34.07 26.73,34.09 25.53,34.09 24.5,35.12 24.5,39.4 24.57,39.48 24.57,40.03 21.88,42.72 6.27,42.72 3.78,45.22 3.78,53.43 4.65,54.3 4.65,61.43 5.41,62.19 8.04,62.19 8.34,61.89 22.39,61.89 25.22,64.72 v1(25.27,64.72)
  BOTTOM w0.15: v1(29.75,64.95) 29.67,64.87 25.42,64.87 v1(25.27,64.72)
DIO7_GLED: length 66.9
  TOP w0.15: J2.1 50.57,68.46 52.24,70.12 v1(54.05,70.12) ; v1(33.3,33.03) 32.72,33.03
  L3 w0.15: P1.4 41.21,68.44 42.72,69.95 48.04,69.95 J2.1 ; v1(33.3,33.03) 34.62,33.03 35.95,34.35 35.95,34.5 35.97,34.52 35.97,35.34 44.71,44.07 46.53,44.07 46.73,44.28 52.23,44.28 53.95,45.99 53.95,47.82 53.92,47.85 53.92,49.57 54.92,50.57 54.92,61.2 55.02,61.3 55.02,67.65 54.57,68.1 54.57,68.18 54.45,68.3 54.45,69.72 v1(54.05,70.12)
DIO8_MISO: length 83.2
  TOP w0.15: 32.72,33.62 v1(34.02,33.62) ; U3.2 v1(30.88,72.65)
  L3 w0.15: v1(30.88,72.65) 30.52,72.65 30.38,72.5 30.38,71.8 31.05,71.12 35.17,71.12 36.1,72.05 36.52,72.05 36.55,72.07 36.9,72.07 36.93,72.05 50.27,72.05 52.72,69.6 52.72,69.57 53.12,69.17 53.12,67.8 53.75,67.18 53.75,64.27 53.72,64.25 53.72,62.55 53.72,62.55 53.72,61.7 53.72,61.7 53.72,60.1 53.68,60.05 53.68,58.95 53.72,58.9 53.72,57.62 53.6,57.49 53.6,54.8 52.07,53.27 J2.14 51.04,54.25 49.99,54.25 49.97,54.27 49.1,54.27 49.08,54.25 44.6,54.25 44.58,54.22 39.27,54.22 35.82,50.78 35.82,50.78 35.57,50.53 35.57,50.53 35.52,50.48 35.52,47.6 34.67,46.75 34.67,39.08 34.63,39.04 34.63,38.91 33.25,37.53 33.25,37.53 33,37.28 33,36.93 33.5,36.43 34.33,35.6 34.33,35.58 34.35,35.55 34.35,34.32 34.33,34.3 34.33,34.28 34.25,34.21 34.04,33.99 34.04,33.84 34.02,33.82 v1(34.02,33.62)
DIO9_MOSI: length 71.6
  TOP w0.15: 32.72,34.12 33.25,34.12 33.27,34.14 v1(33.32,34.14) ; v1(36.72,71.65) U3.5
  L3 w0.15: v1(33.32,34.14) 33.75,34.57 33.75,35.3 33.73,35.33 33.73,35.35 32.9,36.18 32.9,36.18 32.4,36.68 32.4,37.53 33,38.13 33,38.13 34.03,39.16 34.03,39.36 34.07,39.4 34.07,47 34.92,47.85 34.92,50.73 34.97,50.78 39.05,54.85 41.07,56.88 50.96,56.88 J2.12 52.41,55.76 53,56.35 53,57.74 53.12,57.87 53.12,58.65 53.08,58.7 53.08,60.36 53.12,60.41 53.12,61.95 53.12,61.95 53.12,62.3 53.12,62.3 53.12,64.5 53.15,64.52 53.15,66.92 53.1,66.97 51.19,66.97 50.58,67.58 50.58,68.9 49.97,69.51 49.96,69.51 47.82,71.65 v1(36.72,71.65)
DIO10_SCLK: length 89.2
  TOP w0.15: v1(27.52,70.6) 37.07,70.6 37.35,70.88 37.35,71.63 36.83,72.15 U3.6 ; 32.72,34.62 v1(32.15,34.62)
  L3 w0.15: 32.57,40.18 32.57,45.2 32.57,45.36 32.57,45.57 32.57,50.33 27.25,55.65 27.25,59.23 27.12,59.36 27.12,59.96 27.25,60.09 27.25,65.32 27.1,65.47 27.1,70.18 v1(27.52,70.6) ; 32.57,40.18 32.5,40.18 32.29,40.39 31.93,40.39 31.74,40.2 31.4,40.2 31.37,40.18 31.27,40.18 30.51,39.42 29.41,39.42 29.23,39.23 28.47,39.23 28.07,39.62 28.07,41.45 18.92,50.6 18.85,50.6 18.25,51.2 18.25,51.28 15.07,54.45 7.99,54.45 6.76,53.22 J1.13 ; 32.57,40.18 32.57,40.03 32.53,39.99 32.53,39.79 32.38,39.63 32.37,39.63 32.28,39.54 31.65,39.54 30.57,38.46 30.57,38.09 30.22,37.75 30.22,37.47 30.24,37.46 30.24,36.31 30.6,35.95 30.6,35.92 30.85,35.68 30.97,35.68 31.45,35.2 31.45,35.2 32.03,34.62 v1(32.15,34.62)
DIO11_CS: length 43.2
  TOP w0.15: v1(33.32,35.12) 32.72,35.12
  L3 w0.15: J2.6 50.85,62.16 50.85,57.62 50.43,57.2 40.94,57.2 34.72,50.98 34.72,50.95 34.62,50.85 34.62,47.97 33.77,47.12 33.77,39.53 33.73,39.49 33.73,39.29 32.88,38.43 32.87,38.43 32.1,37.66 32.1,36.55 32.6,36.05 33.32,35.33 v1(33.32,35.12)
DIO14_BTN2: length 50.2
  TOP w0.15: J2.18 54.64,48.14 v1(54.65,48.15) ; v1(54.88,69.07) 54.98,69.18 R13.2 ; v1(34.15,36.62) 32.72,36.62
  L3 w0.15: J2.18 51.05,47.12 49.99,47.12 49.97,47.09 45.14,47.09 44.68,46.62 43.74,46.62 37.09,39.97 36.65,39.97 36.25,39.57 36.25,38.71 35.65,38.11 35.65,37.77 35.23,37.35 34.83,37.35 34.38,36.9 34.35,36.9 34.15,36.7 v1(34.15,36.62) ; v1(54.65,48.15) 54.65,49.38 55.77,50.5 55.77,67.32 54.88,68.22 v1(54.88,69.07)
DIO15_BTN1: length 80.1
  TOP w0.15: 32.72,37.12 33.38,37.12 33.39,37.1 v1(33.42,37.1) ; R12.2 v1(9.3,73.2)
  L3 w0.15: v1(33.42,37.1) 34.03,37.1 34.1,37.18 34.2,37.18 34.23,37.2 34.25,37.2 34.7,37.65 35.1,37.65 35.35,37.9 35.35,38.24 35.57,38.46 35.57,44.32 35.67,44.42 35.67,46.21 35.72,46.26 v1(35.72,46.3) 36.42,47 36.42,49.15 36.78,49.5 50.89,49.5 J2.16 ; v1(9.3,73.2) 18.45,73.2 25.27,66.38 25.6,66.38 26.02,65.95 26.02,64.5 26,64.47 26,64.42 25.75,64.17 25.75,53.93 31.35,48.33 31.35,46.43 v1(31.22,46.3)
  BOTTOM w0.15: v1(31.22,46.3) v1(35.72,46.3)
DIO19_CTS: length 53.5
  TOP w0.15: 31.12,39.22 v1(31.12,40.68)
  L3 w0.15: J2.4 50.73,64.57 44.45,64.57 43.7,63.82 43.56,63.68 30.48,63.68 v1(30.2,63.4) ; v1(31.12,40.68) 31.12,40.98 31.97,41.83 31.97,45.19 31.97,45.54 31.97,45.71 31.97,45.72 31.97,50.08 26.4,55.65 26.4,63.22 v1(26.5,63.32)
  BOTTOM w0.15: v1(30.2,63.4) 26.57,63.4 v1(26.5,63.32)
DIO20_FLASH_CS: length 75.8
  TOP w0.15: 30.62,39.22 30.62,40.07 v1(30.6,40.1) ; v1(26.2,73.15) v1(31.27,73.15) R24.1 U3.1
  L3 w0.15: v1(26.2,73.15) 26.32,73.03 26.32,63.75 26.07,63.5 26.07,55.55 31.67,49.95 31.67,45.8 31.67,45.79 31.67,45.62 31.67,45.3 31.67,41.95 30.62,40.9 30.62,40.13 v1(30.6,40.1) ; J2.5 44.85,63.38 44.01,62.54 34.24,62.54 34.2,62.5 33.85,62.5 33.81,62.54 29.94,62.54 29.22,63.25 29.22,71.16 29.99,71.93 29.99,72.87 30.27,73.15 v1(31.27,73.15)
DIO21_SCL: length 35
  TOP w0.15: R3.1 5.12,45.62 5.12,46.93 J1.17 ; 30.12,39.22 30.12,38.68 v1(29.84,38.39)
  L3 w0.15: v1(29.84,38.39) 29.77,38.32 29.45,38.32 29.45,38.33 28.93,38.33 28.93,38.33 28.32,38.33 28.32,38.32 28.09,38.32 27.17,39.25 27.17,40.82 21.02,46.97 7.62,46.97 7.35,47.25 7.22,47.25 J1.17
DIO22: length 32.5
  TOP w0.15: 29.62,39.22 v1(29.62,40.18)
  L3 w0.15: J1.9 7.38,57.25 13.4,57.25 18.85,51.8 18.85,51.45 19.1,51.2 19.45,51.2 29.6,41.05 29.6,40.2 v1(29.62,40.18)
DIO23_ANALOG: length 50.3
  TOP w0.15: 29.12,39.22 v1(29.12,39.82)
  L3 w0.15: v1(29.12,39.82) 29.37,39.82 29.45,39.75 29.8,39.75 30.05,40 30.05,41.1 30.07,41.12 30.07,44.7 25.42,49.35 25.42,53 25.45,53.03 25.45,64.3 25.7,64.55 25.7,64.6 25.72,64.62 25.72,65.83 25.48,66.07 15.05,66.07 13.45,64.47 7.78,64.47 J1.3
DIO24_ANALOG: length 31.4
  TOP w0.15: v1(28.57,39.82) 28.62,39.78 28.62,39.22
  L3 w0.15: J1.11 6.34,55.76 7.53,56.95 13,56.95 18.55,51.4 18.55,51.32 18.97,50.9 19.05,50.9 28.57,41.38 v1(28.57,39.82)
DIO25_ANALOG: length 50.8
  TOP w0.15: 27.12,39.22 27.12,39.6 26.97,39.75 v1(24.15,39.75)
  L3 w0.15: v1(24.15,39.75) 21.47,42.43 6.15,42.43 3.48,45.09 3.48,60.66 3.98,61.15 3.98,63.75 4.75,64.53 6.98,64.53 8.12,63.38 J1.6
DIO26_ANALOG: length 46.3
  TOP w0.15: U1.1 v1(24.92,39.22)
  L3 w0.15: J1.8 8.78,60.84 7.73,61.89 5.69,61.89 4.95,61.15 4.95,54.17 4.08,53.31 4.08,45.34 6.4,43.03 22,43.03 24.92,40.1 v1(24.92,39.22)
DIO27_ANALOG: length 44.2
  TOP w0.15: U1.2 25.22,38.62 v1(25.2,38.64)
  L3 w0.15: J1.10 8.7,58.3 7.6,59.4 5.62,59.4 5.25,59.03 5.25,54.05 4.38,53.18 4.38,45.47 6.52,43.32 22.12,43.32 25.35,40.1 25.35,39.05 25.2,38.9 v1(25.2,38.64)
DIO28: length 39.8
  TOP w0.15: U1.3 v1(25.1,38.12)
  L3 w0.15: J1.12 7.56,54.45 6.08,54.45 4.68,53.06 4.68,45.59 6.65,43.62 22.25,43.62 25.65,40.22 25.65,38.49 25.36,38.2 25.17,38.2 v1(25.1,38.12)
DIO29: length 45.6
  TOP w0.15: v1(25.95,36.15) 25.97,36.12 U1.7
  L3 w0.15: v1(25.95,36.15) 25.95,37.5 26.52,38.07 26.52,38.09 26.55,38.11 26.55,40.6 22.62,44.53 8.46,44.53 7.82,45.16 7.82,46.35 7.22,46.95 5.6,46.95 5.28,47.27 5.28,51.12 5.9,51.73 6.05,51.73 6.15,51.82 7.07,51.82 7.82,51.08 7.82,49.78 8.05,49.55 10.27,49.55 10.82,50.1 10.82,51.15 8.87,53.1 J1.14
DIO30: length 39.6
  TOP w0.15: U1.8 v1(25.95,35.62)
  L3 w0.15: v1(25.95,35.62) 25.87,35.62 25.52,35.97 25.52,36.33 25.62,36.43 25.62,37.6 26.22,38.2 26.22,38.21 26.25,38.24 26.25,40.47 22.5,44.22 8.34,44.22 7.52,45.04 7.52,46.23 7.1,46.65 5.47,46.65 4.98,47.14 4.98,51.24 5.87,52.12 7.43,52.12 J1.16
DIO31: length 32.7
  TOP w0.15: 32.12,39.22 32.12,39.95 v1(32.11,39.97)
  L3 w0.15: J1.15 7.82,49.19 19.66,49.19 27.77,41.07 27.77,39.5 28.34,38.93 29.18,38.93 29.35,38.93 29.54,39.12 30.64,39.12 31.4,39.88 31.5,39.88 31.52,39.9 31.87,39.9 31.92,39.95 32.09,39.95 v1(32.11,39.97)
LP_RESET: length 5.3
  TOP w0.15: R11.2 50.82,57.05 J2.10
RESET: length 110.4
  TOP w0.15: v1(53.35,82.05) 52.65,82.05 ; 52.65,82.05 CR2.2 ; 52.65,82.05 52.57,81.98 52.57,80.42 51.28,79.12 49.77,79.12 49.06,78.41 P6.10 49.06,75.26 50.88,73.44 v1(50.88,70.82) ; U1.4 26.8,37.62 26.81,37.64 v1(27.1,37.64) ; R11.1 R9.1 v1(46.25,55.78)
  L3 w0.15: v1(27.1,37.64) 27.21,37.64 27.57,37.27 27.57,36.93 27.82,36.68 28.06,36.68 28.21,36.53 28.3,36.53 29.72,35.1 29.72,34.6 30.28,34.05 32.8,34.05 33.12,33.72 33.13,33.72 33.14,33.72 33.49,33.72 33.74,33.96 33.74,34.11 34.03,34.4 34.03,34.43 34.05,34.45 34.05,35.43 34.03,35.45 34.03,35.48 33.2,36.3 33.2,36.3 32.7,36.8 32.7,37.41 33.12,37.83 33.13,37.83 34.33,39.04 34.33,39.24 34.38,39.28 34.38,46.87 35.22,47.72 35.22,50.6 35.27,50.65 39.17,54.55 40.4,55.78 v1(46.25,55.78) 46.6,55.78 47.7,54.68 52.92,54.68 53.3,55.05 53.3,57.62 53.42,57.74 53.42,58.78 53.38,58.82 53.38,60.18 53.42,60.22 53.42,61.82 53.42,61.82 53.42,62.43 53.42,62.43 53.42,64.37 53.45,64.4 53.45,67.05 53.09,67.41 51.17,67.41 50.9,67.69 50.9,69.12 50.88,69.14 v1(50.88,70.82) ; v1(53.35,82.05) 53.38,82.07 53.38,82.52 52.82,83.07 49.75,83.07 46.2,86.62 43,86.62 41.47,88.15 32.12,88.15 31.01,87.04 J4.10
RXD: length 80.4
  TOP w0.15: 32.72,35.62 v1(31.63,35.62)
  L3 w0.15: J4.14 25.51,87.04 26.55,86 26.55,84.93 26.65,84.82 26.65,83.67 27.2,83.12 27.2,71.53 27.95,70.78 27.95,66.07 v1(27.52,65.65) 27.52,65.47 27.55,65.45 27.55,59.96 27.42,59.84 27.42,59.48 27.55,59.36 27.55,55.78 32.88,50.45 32.88,39.9 32.83,39.86 32.83,39.66 32.5,39.33 32.5,39.33 32.41,39.24 31.77,39.24 31.25,38.72 31.25,37.72 31.42,37.55 31.42,36.8 31.45,36.78 31.45,35.8 v1(31.62,35.62) ; v1(25.3,65.65) 21.95,62.3 8.35,62.3 8.16,62.49 7.01,62.49 6.33,63.17 J1.5
  BOTTOM w0.15: v1(25.3,65.65) v1(27.52,65.65)
SWO: length 98.6
  TOP w0.15: v1(26.15,82.4) 26.15,82.5 28.02,84.38 J4.11 ; CR2.1 v1(51.85,81.07) ; v1(31.65,40.78) 31.62,40.75 31.62,39.22
  L3 w0.15: J4.11 28.02,83.9 31.78,80.15 45.8,80.15 46.21,80.56 46.26,80.56 46.3,80.6 46.65,80.6 46.69,80.56 49.86,80.56 50.5,81.2 51.72,81.2 v1(51.85,81.07) ; v1(31.65,40.78) 31.65,41.08 32.27,41.7 32.27,45.2 32.27,45.46 32.27,45.64 32.27,45.65 32.27,50.2 26.82,55.65 v1(26.82,58.32) 26.82,63.05 26.92,63.15 26.92,65.22 26.8,65.35 26.8,81.75 v1(26.15,82.4) ; J2.9 v1(29.07,58.3)
  BOTTOM w0.15: v1(26.82,58.32) 26.85,58.3 v1(29.07,58.3)
TCK: length 89.2
  TOP w0.15: v1(34.92,38.07) 34.88,38.12 32.72,38.12 ; v1(48.35,82.02) 46.07,82.02 45.25,81.2 P6.4 v1(45.25,74.94) ; CR2.6 49.9,82.05 49.89,82.04 49.68,82.04 v1(49.67,82.05) ; R5.2 v1(46.32,50.68)
  L3 w0.15: v1(45.25,74.94) 45.45,74.74 45.45,74.37 45.7,74.12 46.07,74.12 46.52,73.68 49.5,73.68 49.77,73.4 49.83,73.4 50.07,73.15 50.07,73.1 53.32,69.85 53.32,69.82 53.72,69.42 53.72,68.05 54.35,67.43 54.35,64.02 54.32,64 54.32,62.8 54.32,62.8 54.32,61.45 54.32,61.45 54.32,59.85 54.28,59.8 54.28,59.2 54.32,59.15 54.32,57.37 54.2,57.24 54.2,52.4 53.65,51.85 48.12,51.85 46.95,50.68 v1(46.32,50.68) 37.38,50.68 36.12,49.42 36.12,47.35 35.27,46.5 35.27,38.59 35.05,38.36 35.05,38.32 34.92,38.2 v1(34.92,38.07) ; v1(49.67,82.05) 48.38,82.05 v1(48.35,82.02) 48.3,82.07 48.3,82.68 45.4,85.57 39.15,85.57 38.88,85.85 36.78,85.85 36.52,86.11 36.52,86.16 J4.6
TDI: length 84.3
  TOP w0.15: v1(52.7,82.55) CR2.3 ; P6.8 47.79,74.93 v1(47.77,74.92) ; R7.2 v1(46.27,45.6) ; 32.72,39.22 v1(36.7,39.22)
  L3 w0.15: 47.78,74.91 v1(47.77,74.92) ; 47.78,74.91 50.29,74.91 50.67,75.3 50.67,78.4 52.7,80.43 v1(52.7,82.55) 52.53,82.72 50.95,82.72 50.94,82.73 50.03,82.73 49.98,82.77 49.62,82.77 49.42,82.98 49.25,82.98 46,86.23 41.77,86.23 40.96,87.04 J4.2 ; 47.78,74.91 48.59,74.1 49.62,74.1 51.65,72.07 51.65,71.95 53.62,69.97 53.62,69.95 54.1,69.47 54.1,68.18 54.27,68 54.27,67.97 54.72,67.53 54.72,61.42 54.62,61.32 54.62,50.7 53.62,49.7 53.62,47.72 53.65,47.7 53.65,46.82 53.5,46.68 48.35,46.68 47.27,45.6 v1(46.27,45.6) 46.22,45.55 44.88,45.55 38.95,39.62 37.57,39.62 37.17,39.22 v1(36.7,39.22)
TDO: length 106.4
  TOP w0.15: R6.2 v1(46.3,48.15) ; CR2.5 v1(49.17,82.55) 49.17,81.3 46.55,78.68 46.52,78.68 46.52,78.67 P6.6 ; v1(32.07,38.51) 32.13,38.57 32.25,38.57 32.3,38.62 32.72,38.62
  L3 w0.15: v1(36.85,48.12) 36.88,48.15 v1(46.3,48.15) ; J4.4 39.18,86.05 39.18,85.99 39.29,85.88 45.75,85.88 49.07,82.55 v1(49.17,82.55) 49.25,82.48 49.85,82.48 49.93,82.4 51.32,82.4 52.3,81.43 52.3,80.92 52.03,80.65 51.67,80.65 51.45,80.88 50.75,80.88 49.55,79.68 48.9,79.68 48.57,79.35 31.4,79.35 28.02,75.97 28.02,71.55 28.55,71.03 28.55,65.65 28.38,65.47 28.38,59.58 28.15,59.36 28.15,56.03 34.2,49.98 v1(34.2,48.15) 34.2,48 33.75,47.55 33.75,47.52 33.47,47.25 33.47,39.65 33.44,39.61 33.44,39.41 32.75,38.73 32.75,38.73 32.66,38.64 32.21,38.64 32.1,38.53 32.08,38.53 v1(32.07,38.51)
  BOTTOM w0.15: v1(36.85,48.12) 36.82,48.15 v1(34.2,48.15)
TMS: length 92
  TOP w0.15: v1(49.7,81.52) 49.73,81.55 CR2.7 ; v1(34.07,37.62) 32.72,37.62 ; v1(43.98,80.75) P6.2 43.95,76.76 v1(43.95,74.88) ; R4.2 v1(46.27,53.22)
  L3 w0.15: J4.8 33.06,87 33.06,86.05 34.48,84.62 34.48,82.84 35.65,81.68 43.05,81.68 v1(43.98,80.75) 44.86,81.63 48.06,81.63 48.5,81.2 49.35,81.2 49.67,81.52 49.7,81.52 v1(49.7,81.52) ; v1(43.95,74.88) 43.95,74.62 45.3,73.28 46.33,73.28 47.05,72.55 50.2,72.55 53.02,69.72 53.02,69.7 53.42,69.3 53.42,67.93 54.05,67.3 54.05,64.15 54.02,64.12 54.02,62.68 54.02,62.68 54.02,61.57 54.02,61.57 54.02,59.97 53.98,59.93 53.98,59.07 54.02,59.03 54.02,57.49 53.9,57.37 53.9,52.53 53.54,52.17 48.23,52.17 47.17,53.22 v1(46.27,53.22) 39.5,53.22 35.82,49.55 35.82,47.47 34.97,46.62 34.97,38.71 34.84,38.57 34.72,38.57 34.47,38.33 34.47,38.22 34.06,37.8 34.06,37.64 v1(34.07,37.62)
TXD: length 78.3
  TOP w0.15: v1(31.92,36.12) 31.95,36.1 32.17,36.1 32.19,36.12 32.72,36.12
  L3 w0.15: v1(31.92,36.12) 31.75,36.3 31.75,36.9 31.72,36.93 31.72,37.67 31.55,37.85 31.55,38.59 31.9,38.94 32.53,38.94 32.62,39.03 32.63,39.03 33.13,39.54 33.13,39.74 33.17,39.78 33.17,50.58 27.85,55.9 v1(27.85,59.66) 27.85,65.37 28.25,65.77 28.25,70.9 27.5,71.65 27.5,83.25 26.97,83.77 26.97,84.94 27.1,85.06 27.1,86.12 J4.12 ; J1.7 6.71,60.84 7.88,59.68 v1(24.62,59.68)
  BOTTOM w0.15: v1(24.62,59.68) 24.95,59.68 24.97,59.66 v1(27.85,59.66)
WMCU_VDD: length 184.7
  TOP w0.15: v1(18.95,40.78) 19.1,40.78 19.35,41.03 FL2.2
  TOP w0.25: R25.1 36.57,74.38 v1(36.57,74.88) ; R22.2 v1(37.95,73.71) ; v1(51.15,80.3) 51.15,81.4 ; v1(31.25,71.6) 31.76,71.6 R23.2
  TOP w0.5: v1(43,72.94) P6.1 ; R24.2 31.45,74.07 30.47,75.05 v1(28.5,75.05) ; v1(4.38,42.35) 3.7,42.35 3.43,42.62 R2.2 R3.2
  L3 w0.5: v1(31.25,71.6) 33.21,73.56 33.21,74.37 ; v1(28.5,75.05) 29.19,74.37 33.21,74.37 ; J4.16 22.94,86.89 21.7,85.65 21.7,79.5 v1(26.15,75.05) 25.27,74.18 9.15,74.18 8.65,73.68 8.65,71.35 10.4,69.6 10.4,67.74 9.89,67.24 7.56,67.24 J1.1 2.65,64.78 2.65,44.07 v1(4.38,42.35) 4.38,42.3 4.88,41.8 7.85,41.8 8.88,40.78 v1(18.95,40.78) v1(18.95,41.3) ; 37.95,75.75 v1(37.95,73.71) ; 37.95,75.75 43.02,75.75 ; 37.95,75.75 37.08,74.88 v1(36.57,74.88) 35.53,74.88 35.05,74.4 33.24,74.4 33.21,74.37 ; 43.02,75.75 v1(50.17,75.75) 50.17,79.32 v1(51.15,80.3) ; 43.02,75.75 43.02,72.96 v1(43,72.94) ; v1(51.52,75.75) 51.52,73.5 56.6,68.43 56.6,45.32 54.02,42.75 51.68,42.75 50.67,41.75 50.67,36.84 P3.1
  BOTTOM w0.5: v1(51.52,75.75) v1(50.17,75.75) ; v1(26.15,75.05) v1(28.5,75.05)
XDS_BOARDID_SCL: length 13.5
  TOP w0.15: U4.1 11.95,83.62 13.22,82.35 20.79,82.35 J4.15
XDS_BOARDID_SDA: length 9
  TOP w0.15: J4.17 18.6,82.7 14.45,82.7 13.85,83.3 U4.3
N3109894: length 2.2
  TOP w0.15: R4.1 49.53,53.22 J2.13
N3109960: length 2.2
  TOP w0.15: R5.1 49.53,50.68 J2.15
N3110034: length 2.2
  TOP w0.15: J2.17 49.52,48.15 R6.1
N3110086: length 2.2
  TOP w0.15: R7.1 J2.19
N3110356: length 22.9
  TOP w0.15: R15.2 45.22,85.27 42.65,82.7 42.65,73.27 42.52,73.14 42.52,72.75 43.17,72.1 43.17,71.35 45.52,69 45.52,67.68 P1.1
N3110380: length 20.7
  TOP w0.15: R14.2 45.6,86.55 45.15,86.55 41.85,83.25 41.85,70.34 P1.3
N3110768: length 1.3
  TOP w0.15: SW1.4 5.53,73.2 R12.1
N3110772: length 4.1
  TOP w0.15: R13.1 55.45,70.1 54.55,71 54.55,73.03 54.4,73.18 SW2.3
N3110876: length 2
  TOP w0.15: R14.1 48.17,86.52 CR4.2
N3110880: length 2
  TOP w0.15: R15.1 48.17,85.27 CR5.2
N3111246: length 2
  TOP w0.25: U3.8 C55.1 35.99,73.16 R25.2
N3111262: length 2.7
  TOP w0.15: R22.1 U3.7
N3111266: length 1.1
  TOP w0.15: U3.3 R23.1
N3450237: length 8.6
  TOP w0.15: J5.1 19.97,30.32 ; 28.55,30.32 C56.1
  TOP w0.3: 19.97,30.32 28.55,30.32
N3450301: length 1.3
  TOP w0.15: C57.1 C56.2
  TOP w0.3: C56.2 29.12,30.37 C1.1 L1.2
N3495961: length 1.9
  TOP w0.3: C57.2 29.12,28.62 Z9.2 29.15,28.59 Z10.1
N3495979: length 3.2
  TOP w0.15: A2.1 29.12,24.25 v1(29.1,24.22)
  TOP w0.3: Z10.2 Z11.1 29.15,25.78 A2.1
  vias: v1(11.2,2.18) v1(11.25,17.07) v1(11.27,14.57) v1(11.27,12.3) v1(11.22,7.12) v1(11.22,4.78) v1(15.92,17.25) v1(15.97,12.35) v1(16.17,7.22) v1(16.2,2.12) v1(20.97,7.38) v1(20.97,2.15) v1(21,12.3) v1(21.1,17.22) v1(25.02,12.3) v1(25.12,17.3) v1(25.2,7.3) v1(25.27,2.22) v1(29.07,20.57) v1(29,17.38) v1(29.17,12.35) v1(29.4,2.18) v1(29.45,7.25) v1(33.77,12.38) v1(33.75,2.32) v1(34.05,7.35) v1(38.35,12.35) v1(38.38,2.38) v1(38.52,7.28) v1(42.25,2.3) v1(42.5,12.38) v1(42.8,7.22) v1(47.05,12.32) v1(47.05,9.57) v1(47.02,7.22) v1(47.05,2.3)
N3510597: length 0.8
  TOP w0.3: L1.1 29.12,33.03

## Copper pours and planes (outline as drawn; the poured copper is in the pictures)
GND on TOP: 0.5,87.99 0.65,88.34 1,88.49 57.5,88.49 57.85,88.34 58,87.99 58,81.6 57.74,80.1 57.01,78.76 55.8,75.3 57.01,71.84 57.74,70.5 58,69 58,26.55 29.77,26.55 29.77,32.62 28.47,32.62 28.47,30.97 22.6,30.97 21.64,32.52 19.92,33.13 17.17,30.38 19.92,27.62 21.62,28.19 22.62,29.68 28.47,29.68 28.47,26.55 0.5,26.55 0.5,69 0.76,70.5 1.49,71.84 2.7,75.3 1.49,78.76 0.76,80.1 0.5,81.6 ; 6 cut-outs
VDDS on TOP: 28.27,40.53 28.27,41.53 20.88,41.53 20.88,40.53
VDDS on TOP: 27.47,41.5 27.47,38.99 28.27,38.99 28.27,41.5
WMCU_VDD on TOP: 18.7,41.53 18.7,40.53 20.22,40.53 20.22,41.53
N3495979 on TOP (solid shape): 30.12,16.25 12.12,16.25 12.12,13.25 48.12,13.25 48.12,6.25 12.12,6.25 12.12,3.25 48.12,3.25 48.12,1.25 10.12,1.25 10.12,8.25 46.12,8.25 46.12,11.25 10.12,11.25 10.12,18.25 28.12,18.25 28.12,25.25 30.12,25.25
N3495979 on BOTTOM (solid shape): 30.12,16.25 12.12,16.25 12.12,13.25 48.12,13.25 48.12,6.25 12.12,6.25 12.12,3.25 48.12,3.25 48.12,1.25 10.12,1.25 10.12,8.25 46.12,8.25 46.12,11.25 10.12,11.25 10.12,18.25 28.12,18.25 28.12,25.25 30.12,25.25

Small or netless copper shapes (teardrops, artwork), in the pictures only: 115 on TOP, 14 on BOTTOM, 1 on L2, 133 on L3

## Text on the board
Ref Des/Silkscreen Bottom: J1 | 1 | 10 | 21 | 30 | J3 | J4 | 31 | 40 | 11 | 20 | J2 | DIO23 | DIO22 | DIO24 | DIO12 | DIO13 | DIO26 | DIO1 | DIO2 | DIO25 | DIO27 | DIO28 | DIO29 | DIO30 | DIO6 | DIO20 | DIO18 | BPRST | DIO7 | DIO4 | DIO19 | DIO11 | DIO9 | DIO8 | DIO15 | DIO14 | LPRST | DIO10 | DIO31 | DIO21 | DIO5 | TDI | TMS | TCK | TDO
User.Comments: Rev. A | Milling tool 2.0 mm TYP | MCU112 | RED | BOTTOM LAYER
Ref Des/Silkscreen Top: J1 | 10 | 1 | 21 | 30 | J3 | J4 | 40 | 31 | 20 | 11 | J2 | 2 | GND | 5V | 3V3 | RXD | TXD | SWO | nRST | GPIO3 | TMS | GPIO2 | TCK | GPIO1 | TDO | TDI | DIO13 | DIO23 | DIO12 | DIO22 | DIO24 | DIO15 | BTN-1 | DIO25 | DIO26 | DIO27 | DIO28 | DIO29 | DIO30 | DIO1 | DIO2 | LP-EM-CC1312PSIP | Rev: A  MCU112 | >----- LC filter only for 868 MHz | Optional for 915 MHz | BPRST | DIO20 | DIO4 | DIO18 | Target In | Green: DIO7 | Red: DIO6 | DIO7 | DIO6 | LPRST | DIO19 | DIO11 | DIO9 | DIO8 | DIO14 | DIO21 | DIO31 | DIO5 | DIO10 | Extension | BTN-2 | LEDs
XSECTION_CHART: L1: TOP CONDUCTOR - COPPER + PLATING 0.035 MM | *  DIELECTRIC - FR-4 0.175 MM (TOP PRIORITY,  AFTER PRESS) | L2: L2 PLANE - COPPER 0.035 MM | *  DIELECTRIC - FR-4 1.11 MM | L3: L3 PLANE - COPPER 0.035 MM | *  DIELECTRIC - FR-4 0.175 MM | L4: BOTTOM CONDUCTOR - COPPER + PLATING 0.035 MM | DESIGN CROSS SECTION CHART | ___________________________ | TOTAL THICKNESS 1.6 MM
PAGE_OUTLINE: LP-EM-CC1312PSIP
User.27: FIGURE | FINISHED_SIZE | 0.2 | 1.05 | 1.1 | 3.2 | 0.899 | DRILL CHART: TOP to BOTTOM | ALL UNITS ARE IN MILLIMETERS | PLATED | NON-PLATED | QTY | 592 | 70 | 1 | 4
